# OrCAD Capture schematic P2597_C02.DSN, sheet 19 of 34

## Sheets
19 15_Serial port and JTAG: size Custom
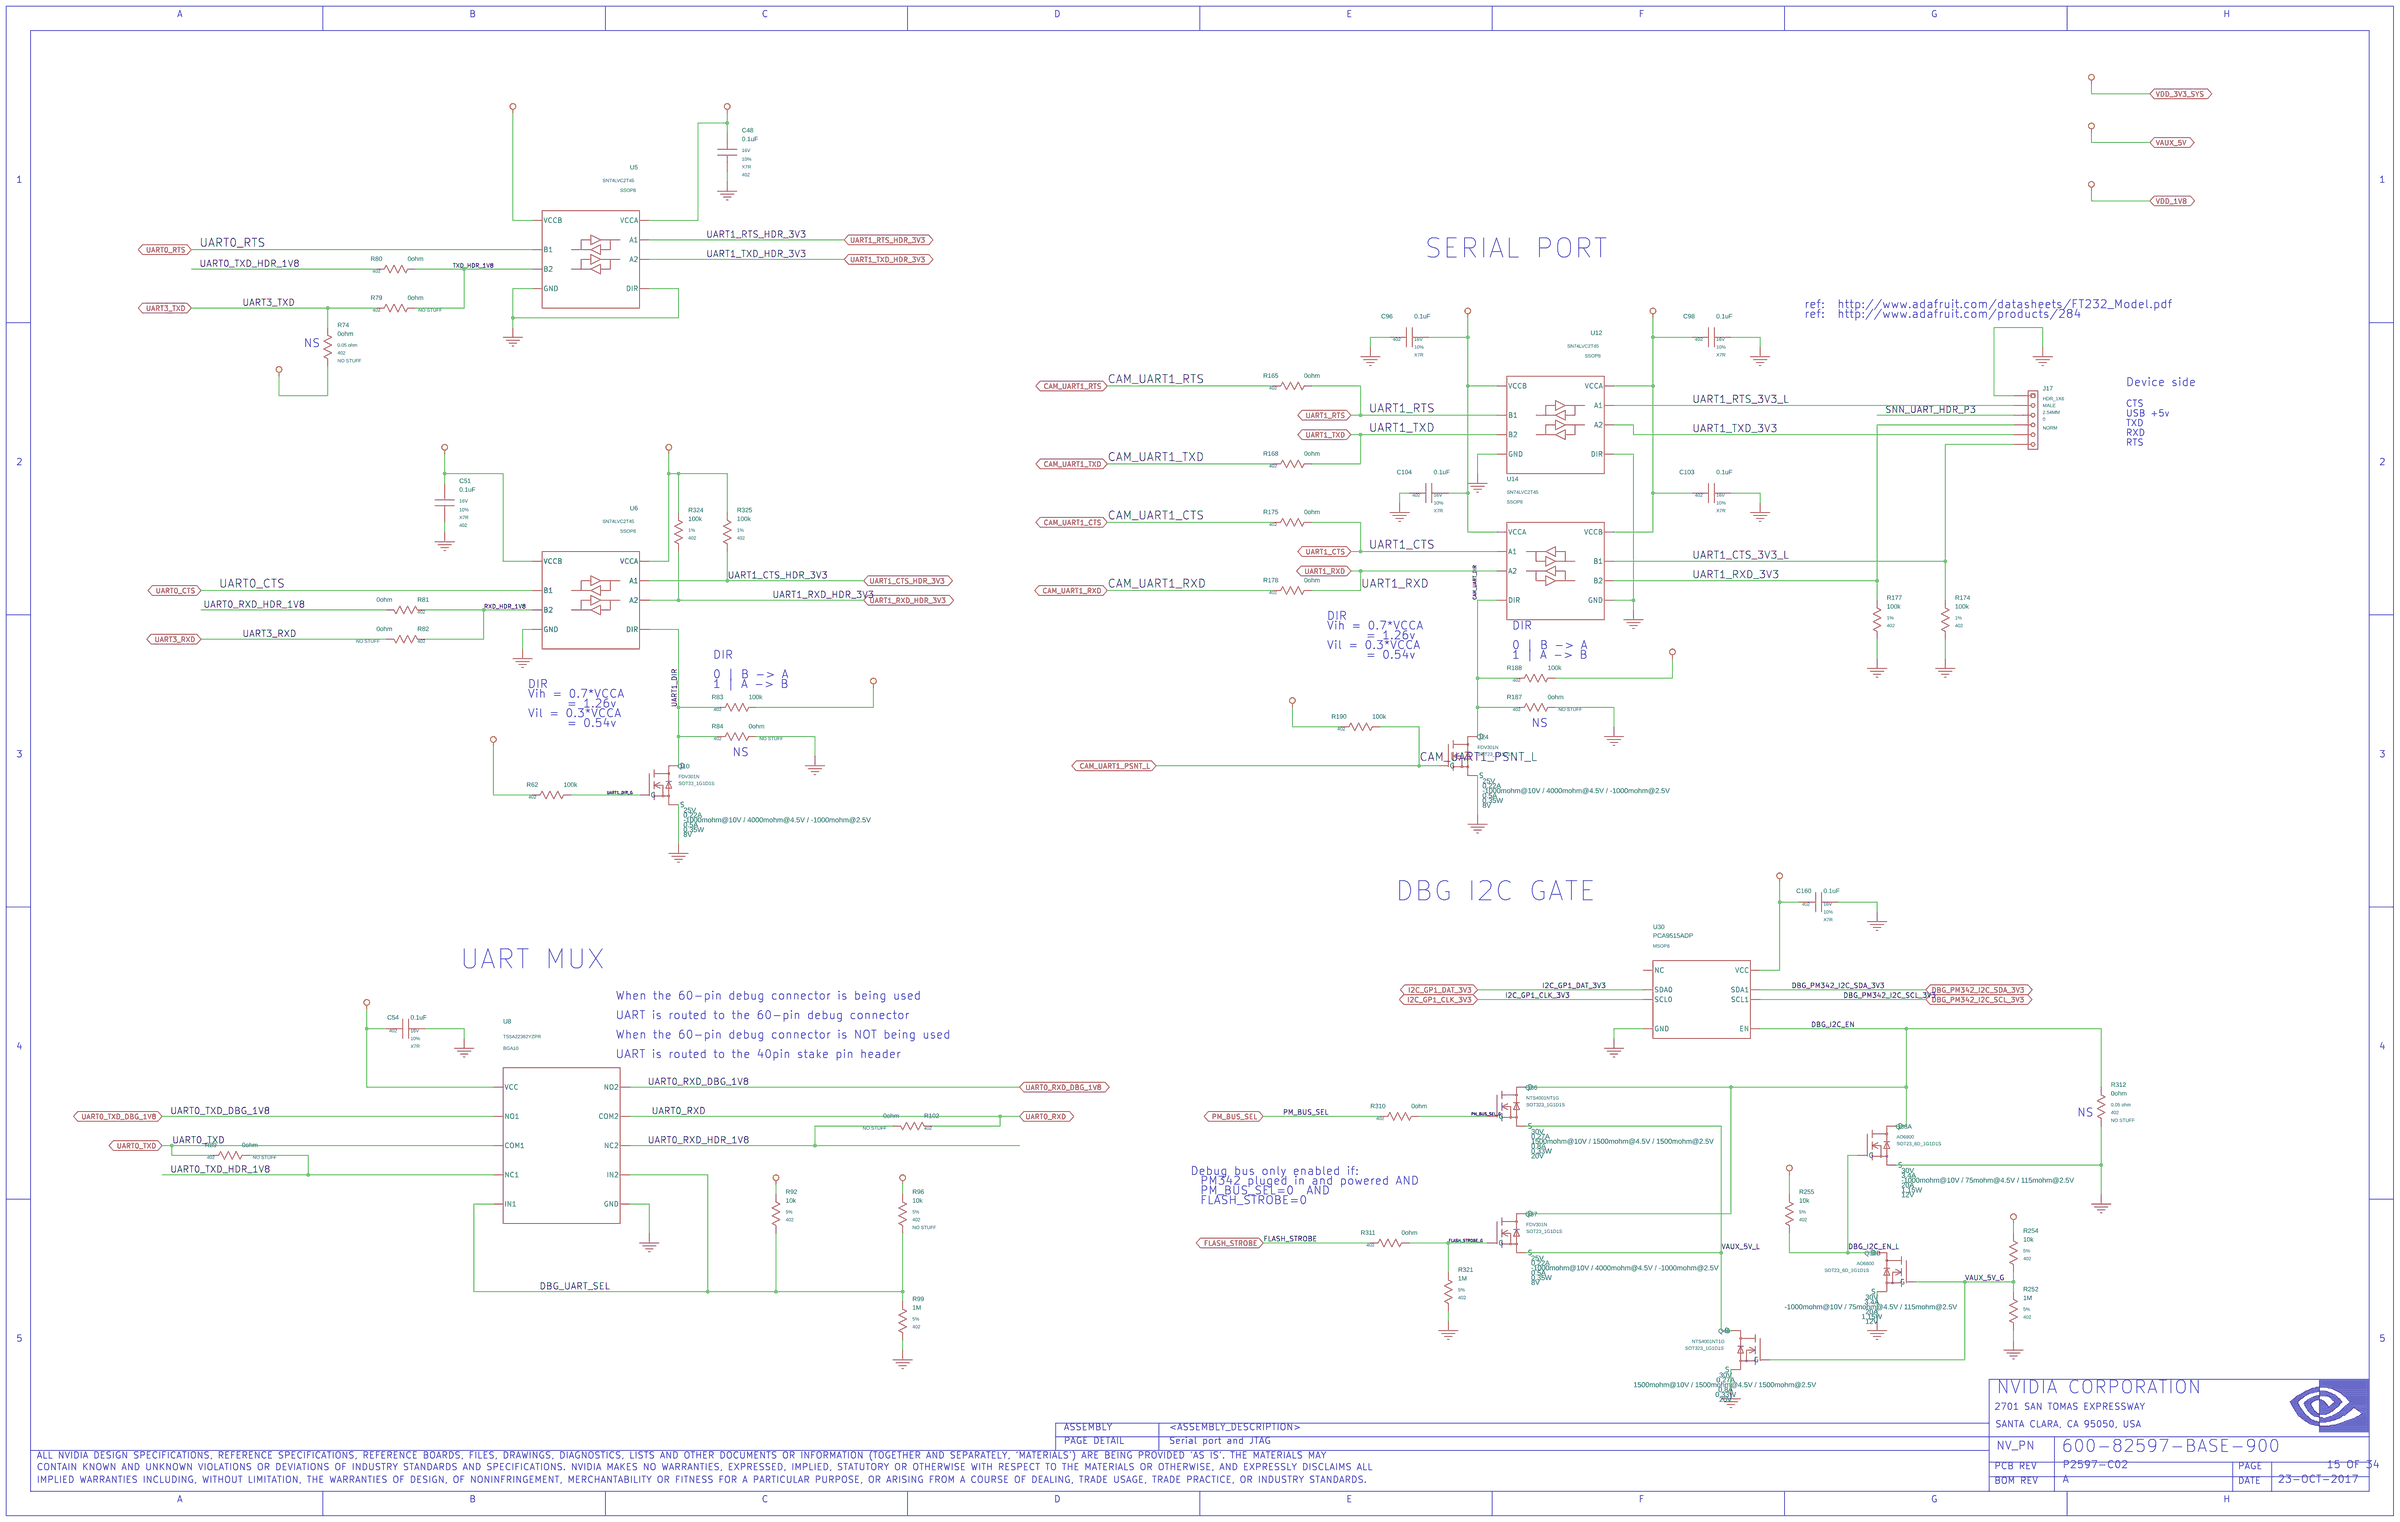
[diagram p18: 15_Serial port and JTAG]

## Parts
C48  0.1uF  [402]
C51  0.1uF  [402]
C54  0.1uF  [402]
C96  0.1uF  [402]
C98  0.1uF  [402]
C103  0.1uF  [402]
C104  0.1uF  [402]
C160  0.1uF  [402]
J17  HDR_1X6  [CON_HDR_001X006_TH_ST_M_P025]
Q10  Q_FET_N_ENH  [SOT23]
Q24  Q_FET_N_ENH  [SOT23]
Q36  Q_FET_N_ENH  [SOT323]
Q37  Q_FET_N_ENH  [SOT23]
Q38  Q_FET_N_ENH  [SOT23_6]  (sections A,B)
Q40  Q_FET_N_ENH  [SOT323]
R62  100k  [402]
R74  0ohm  [402]
R79  0ohm  [402]
R80  0ohm  [402]
R81  0ohm  [402]
R82  0ohm  [402]
R83  100k  [402]
R84  0ohm  [402]
R89  0ohm  [402]
R92  10k  [402]
R96  10k  [402]
R99  1M  [402]
R102  0ohm  [402]
R165  0ohm  [402]
R168  0ohm  [402]
R174  100k  [402]
R175  0ohm  [402]
R177  100k  [402]
R178  0ohm  [402]
R187  0ohm  [402]
R188  100k  [402]
R190  100k  [402]
R252  1M  [402]
R254  10k  [402]
R255  10k  [402]
R310  0ohm  [402]
R311  0ohm  [402]
R312  0ohm  [402]
R321  1M  [402]
R324  100k  [402]
R325  100k  [402]
U5  U_LEVSHFT_3STATE  [XSOP08_P065_030X028]
U6  U_LEVSHFT_3STATE  [XSOP08_P065_030X028]
U8  U_SW_ANA_SPDT  [BGA_0010_P050_013X020_MARK_A3]
U12  U_LEVSHFT_3STATE  [XSOP08_P065_030X028]
U14  U_LEVSHFT_3STATE  [XSOP08_P065_030X028]
U30  U_I2C_PCA9515A  [XSOP08_P065_030X030]

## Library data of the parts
C48 = C: ASSEMBLY: DEBUG; CDS_LIB: discrete; CDS_PART_NAME: C_0402-0.1UF,X7R,10%,16V,036-0014-000; CDS_PHYS_PART_NAME: C_0402-0.1UF,X7R,10%,16V,036-0014-000-0.1UF,036-0014-000; CDS_SEC: 1; DEVICE_TYPENAME: C_0402-01UFX7R1016V036-0014-000-01UF036-0014-000; DRAWING: @P2597_C02_LIB.P2597_C02(SCH_1):PAGE15; MAT: X7R; MAX_VOLTAGE: 16V; NV_PN: 036-0014-000; PATH: I346; PHYS_PAGE: 15; ROT: 0; SEC: 1; SIGNAL_MODEL: nv_cap; TOL: 10%; VER: 1; XY: (-7200,7550)
C51 = C: ASSEMBLY: DEBUG; CDS_LIB: discrete; CDS_PART_NAME: C_0402-0.1UF,X7R,10%,16V,036-0014-000; CDS_PHYS_PART_NAME: C_0402-0.1UF,X7R,10%,16V,036-0014-000-0.1UF,036-0014-000; CDS_SEC: 1; DEVICE_TYPENAME: C_0402-01UFX7R1016V036-0014-000-01UF036-0014-000; DRAWING: @P2597_C02_LIB.P2597_C02(SCH_1):PAGE15; MAT: X7R; MAX_VOLTAGE: 16V; NV_PN: 036-0014-000; PATH: I359; PHYS_PAGE: 15; ROT: 0; SEC: 1; SIGNAL_MODEL: nv_cap; TOL: 10%; VER: 1; XY: (-8650,5750)
C54 = C#1: ASSEMBLY: DEBUG; CDS_LIB: discrete; CDS_PART_NAME: C_0402-0.1UF,X7R,10%,16V,036-0014-000; CDS_PHYS_PART_NAME: C_0402-0.1UF,X7R,10%,16V,036-0014-000-0.1UF,036-0014-000; CDS_SEC: 1; CHIPS_PART_NAME: C; DEVICE_TYPENAME: C_0402-01UFX7R1016V036-0014-000-01UF036-0014-000; DRAWING: @P2597_C02_LIB.P2597_C02(SCH_1):PAGE15; ESL: N/A; ESR: N/A; MAT: X7R; MAX_VOLTAGE: 16V; NV_PN: 036-0014-000; PATH: I372; PHYS_PAGE: 15; ROT: 0; SEC: 1; SIGNAL_MODEL: nv_cap; TOL: 10%; VER: 2; XY: (-8850,3050)
C96 = C#1: ASSEMBLY: DEBUG; CDS_LIB: discrete; CDS_PART_NAME: C_0402-0.1UF,X7R,10%,16V,036-0014-000; CDS_PHYS_PART_NAME: C_0402-0.1UF,X7R,10%,16V,036-0014-000-0.1UF,036-0014-000; CDS_SEC: 1; CHIPS_PART_NAME: C; DEVICE_TYPENAME: C_0402-01UFX7R1016V036-0014-000-01UF036-0014-000; DRAWING: @P2597_C02_LIB.P2597_C02(SCH_1):PAGE15; MAT: X7R; MAX_VOLTAGE: 16V; NV_PN: 036-0014-000; PATH: I89; PHYS_PAGE: 15; ROT: 0; SEC: 1; SIGNAL_MODEL: nv_cap; TOL: 10%; VER: 2; XY: (-3700,6600)
C98 = C#1: ASSEMBLY: DEBUG; CDS_LIB: discrete; CDS_PART_NAME: C_0402-0.1UF,X7R,10%,16V,036-0014-000; CDS_PHYS_PART_NAME: C_0402-0.1UF,X7R,10%,16V,036-0014-000-0.1UF,036-0014-000; CDS_SEC: 1; CHIPS_PART_NAME: C; DEVICE_TYPENAME: C_0402-01UFX7R1016V036-0014-000-01UF036-0014-000; DRAWING: @P2597_C02_LIB.P2597_C02(SCH_1):PAGE15; MAT: X7R; MAX_VOLTAGE: 16V; NV_PN: 036-0014-000; PATH: I91; PHYS_PAGE: 15; ROT: 0; SEC: 1; SIGNAL_MODEL: nv_cap; TOL: 10%; VER: 2; XY: (-2150,6600)
C103 = C#1: ASSEMBLY: DEBUG; CDS_LIB: discrete; CDS_PART_NAME: C_0402-0.1UF,X7R,10%,16V,036-0014-000; CDS_PHYS_PART_NAME: C_0402-0.1UF,X7R,10%,16V,036-0014-000-0.1UF,036-0014-000; CDS_SEC: 1; CHIPS_PART_NAME: C; DEVICE_TYPENAME: C_0402-01UFX7R1016V036-0014-000-01UF036-0014-000; DRAWING: @P2597_C02_LIB.P2597_C02(SCH_1):PAGE15; MAT: X7R; MAX_VOLTAGE: 16V; NV_PN: 036-0014-000; PATH: I92; PHYS_PAGE: 15; ROT: 0; SEC: 1; SIGNAL_MODEL: nv_cap; TOL: 10%; VER: 2; XY: (-2150,5800)
C104 = C#1: ASSEMBLY: DEBUG; CDS_LIB: discrete; CDS_PART_NAME: C_0402-0.1UF,X7R,10%,16V,036-0014-000; CDS_PHYS_PART_NAME: C_0402-0.1UF,X7R,10%,16V,036-0014-000-0.1UF,036-0014-000; CDS_SEC: 1; CHIPS_PART_NAME: C; DEVICE_TYPENAME: C_0402-01UFX7R1016V036-0014-000-01UF036-0014-000; DRAWING: @P2597_C02_LIB.P2597_C02(SCH_1):PAGE15; MAT: X7R; MAX_VOLTAGE: 16V; NV_PN: 036-0014-000; PATH: I90; PHYS_PAGE: 15; ROT: 0; SEC: 1; SIGNAL_MODEL: nv_cap; TOL: 10%; VER: 2; XY: (-3600,5800)
C160 = C#1: ASSEMBLY: DEBUG; CDS_LIB: discrete; CDS_PART_NAME: C_0402-0.1UF,X7R,10%,16V,036-0014-000; CDS_PHYS_PART_NAME: C_0402-0.1UF,X7R,10%,16V,036-0014-000-0.1UF,036-0014-000; CDS_SEC: 1; CHIPS_PART_NAME: C; DEVICE_TYPENAME: C_0402-01UFX7R1016V036-0014-000-01UF036-0014-000; DRAWING: @P2597_C02_LIB.P2597_C02(SCH_1):PAGE15; ESL: N/A; ESR: N/A; MAT: X7R; MAX_VOLTAGE: 16V; NV_PN: 036-0014-000; PATH: I446; PHYS_PAGE: 15; ROT: 0; SEC: 1; SIGNAL_MODEL: nv_cap; TOL: 10%; VER: 2; XY: (-1600,3700)
J17 = HDR_1X6: ANGLE: 0; ASSEMBLY: DEBUG; CDS_LIB: electro_mechanic; CDS_PART_NAME: HDR_1X6_NORM-HDR_1X6,MALE,2.54MM,0,YES,NO,NO,450V,3.0A,074-0050-000; CDS_PHYS_PART_NAME: HDR_1X6_NORM-HDR_1X6,MALE,2.54MM,0,YES,NO,NO,450V,3.0A,074-0050-000-074-0050-000; CDS_SEC: 1; DEVICE_TYPENAME: HDR_1X6_NORM-HDR_1X6MALE254MM0YESNONO450V30A074-0050-000-074-0050-000; DRAWING: @P2597_C02_LIB.P2597_C02(SCH_1):PAGE15; GENDER: MALE; LATCHING: NO; MAX_CURRENT: 3.0A; MAX_VOLTAGE: 450V; NV_PN: 074-0050-000; PACK_TYPE: NORM; PATH: I302; PHYS_PAGE: 15; PITCH: 2.54MM; REFLOW: YES; ROT: 0; SEC: 1; SEC_TYPE: NORM; SHROUDED: NO; VER: 1; XY: (-500,6300)
Q10 = Q_FET_N_ENH#2: ASSEMBLY: DEBUG; CDS_LIB: discrete; CDS_PART_NAME: Q_FET_N_ENH_SOT23_1G1D1S-FDV301N,25V,-1000MOHM@10V / 4000MOHM@4.5V / -1000MOHM@2.5V,0.22A,0.5A,8V,0.35W,[ ]@10V / [ ]@4.5V / [A; CDS_PHYS_PART_NAME: Q_FET_N_ENH_SOT23_1G1D1S-FDV301N,25V,-1000MOHM@10V / 4000MOHM@4.5V / -1000MOHM@2.5V,0.22A,0.5A,8V,0.35W,[ ]@10V / [ ]@4.5V / [B; CDS_SEC: 1; CONTINUOUS_CURRENT: 0.22A; CaptureCellPackProp: Q_FET_N_ENH__sym_2##2; DEVICE_TYPENAME: Q_FET_N_ENH_SOT23_1G1D1S-FDV301N25V-1000MOHM10V4000MOHM45V-1000MOHM25V022A05A8V035W10V45VB; DRAWING: @P2597_C02_LIB.P2597_C02(SCH_1):PAGE15; MAX_CURRENT: 0.5A; MAX_VOLTAGE: 25V; MAX_WATTAGE: 0.35W; NV_NAME: FDV301N; NV_PN: 300-0494-000; PACK_TYPE: SOT23_1G1D1S; PATH: I426; PHYS_PAGE: 15; Q_G: [ ]@10V / [ ]@4.5V / [ ]@2.5V; ROT: 0; R_DS_ON: -1000mohm@10V / 4000mohm@4.5V / -1000mohm@2.5V; SEC: 1; VER: 2; V_BE_GS: 8V; XY: (-7550,4300)
Q24 = Q_FET_N_ENH#2: ASSEMBLY: DEBUG; CDS_LIB: discrete; CDS_PART_NAME: Q_FET_N_ENH_SOT23_1G1D1S-FDV301N,25V,-1000MOHM@10V / 4000MOHM@4.5V / -1000MOHM@2.5V,0.22A,0.5A,8V,0.35W,[ ]@10V / [ ]@4.5V / [A; CDS_PHYS_PART_NAME: Q_FET_N_ENH_SOT23_1G1D1S-FDV301N,25V,-1000MOHM@10V / 4000MOHM@4.5V / -1000MOHM@2.5V,0.22A,0.5A,8V,0.35W,[ ]@10V / [ ]@4.5V / [B; CDS_SEC: 1; CONTINUOUS_CURRENT: 0.22A; CaptureCellPackProp: Q_FET_N_ENH__sym_2##2; DEVICE_TYPENAME: Q_FET_N_ENH_SOT23_1G1D1S-FDV301N25V-1000MOHM10V4000MOHM45V-1000MOHM25V022A05A8V035W10V45VB; DRAWING: @P2597_C02_LIB.P2597_C02(SCH_1):PAGE15; MAX_CURRENT: 0.5A; MAX_VOLTAGE: 25V; MAX_WATTAGE: 0.35W; NV_NAME: FDV301N; NV_PN: 300-0494-000; PACK_TYPE: SOT23_1G1D1S; PATH: I410; PHYS_PAGE: 15; Q_G: [ ]@10V / [ ]@4.5V / [ ]@2.5V; ROT: 0; R_DS_ON: -1000mohm@10V / 4000mohm@4.5V / -1000mohm@2.5V; SEC: 1; VER: 2; V_BE_GS: 8V; XY: (-3450,4450)
Q36 = Q_FET_N_ENH#2: ASSEMBLY: DEBUG; CDS_LIB: discrete; CDS_PART_NAME: Q_FET_N_ENH_SOT323_1G1D1S-NTS4001NT1G,30V,1500MOHM@10V / 1500MOHM@4.5V / 1500MOHM@2.5V,0.27A,0.8A,20V,0.33W,[ ]@10V / [ ]@4.5VA; CDS_PHYS_PART_NAME: Q_FET_N_ENH_SOT323_1G1D1S-NTS4001NT1G,30V,1500MOHM@10V / 1500MOHM@4.5V / 1500MOHM@2.5V,0.27A,0.8A,20V,0.33W,[ ]@10V / [ ]@4.5VB; CDS_SEC: 1; CONTINUOUS_CURRENT: 0.27A; CaptureCellPackProp: Q_FET_N_ENH__sym_2##2; DEVICE_TYPENAME: Q_FET_N_ENH_SOT323_1G1D1S-NTS4001NT1G30V1500MOHM10V1500MOHM45V1500MOHM25V027A08A20V033W10V45VB; DRAWING: @P2597_C02_LIB.P2597_C02(SCH_1):PAGE15; MAX_CURRENT: 0.8A; MAX_VOLTAGE: 30V; MAX_WATTAGE: 0.33W; NV_NAME: NTS4001NT1G; NV_PN: 300-0485-000; PACK_TYPE: SOT323_1G1D1S; PATH: I481; PHYS_PAGE: 15; Q_G: [ ]@10V / [ ]@4.5V / [ ]@2.5V; ROT: 0; R_DS_ON: 1500mohm@10V / 1500mohm@4.5V / 1500mohm@2.5V; SEC: 1; SEC_TYPE: SOT323_1G1D1S; VER: 2; V_BE_GS: 20V; XY: (-3200,2650)
Q37 = Q_FET_N_ENH#2: ASSEMBLY: DEBUG; CDS_LIB: discrete; CDS_PART_NAME: Q_FET_N_ENH_SOT23_1G1D1S-FDV301N,25V,-1000MOHM@10V / 4000MOHM@4.5V / -1000MOHM@2.5V,0.22A,0.5A,8V,0.35W,[ ]@10V / [ ]@4.5V / [A; CDS_PHYS_PART_NAME: Q_FET_N_ENH_SOT23_1G1D1S-FDV301N,25V,-1000MOHM@10V / 4000MOHM@4.5V / -1000MOHM@2.5V,0.22A,0.5A,8V,0.35W,[ ]@10V / [ ]@4.5V / [B; CDS_SEC: 1; CONTINUOUS_CURRENT: 0.22A; CaptureCellPackProp: Q_FET_N_ENH__sym_2##2; DEVICE_TYPENAME: Q_FET_N_ENH_SOT23_1G1D1S-FDV301N25V-1000MOHM10V4000MOHM45V-1000MOHM25V022A05A8V035W10V45VB; DRAWING: @P2597_C02_LIB.P2597_C02(SCH_1):PAGE15; MAX_CURRENT: 0.5A; MAX_VOLTAGE: 25V; MAX_WATTAGE: 0.35W; NV_NAME: FDV301N; NV_PN: 300-0494-000; PACK_TYPE: SOT23_1G1D1S; PATH: I480; PHYS_PAGE: 15; Q_G: [ ]@10V / [ ]@4.5V / [ ]@2.5V; ROT: 0; R_DS_ON: -1000mohm@10V / 4000mohm@4.5V / -1000mohm@2.5V; SEC: 1; SEC_TYPE: SOT23_1G1D1S; VER: 2; V_BE_GS: 8V; XY: (-3200,2000)
Q38 = Q_FET_N_ENH: ASSEMBLY: DEBUG; CDS_LIB: discrete; CDS_PART_NAME: Q_FET_N_ENH_SOT23_6D_1G1D1S-AO6800,30V,-1000MOHM@10V / 75MOHM@4.5V / 115MOHM@2.5V,3.4A,20A,12V,1.15W,[ ]@10V / [ ]@4.5V / [ ]@A; CDS_PHYS_PART_NAME: Q_FET_N_ENH_SOT23_6D_1G1D1S-AO6800,30V,-1000MOHM@10V / 75MOHM@4.5V / 115MOHM@2.5V,3.4A,20A,12V,1.15W,[ ]@10V / [ ]@4.5V / [ ]@B; CDS_SEC: 2; CONTINUOUS_CURRENT: 3.4A; DEVICE_TYPENAME: Q_FET_N_ENH_SOT23_6D_1G1D1S-AO680030V-1000MOHM10V75MOHM45V115MOHM25V34A20A12V115W10V45VB; DRAWING: @P2597_C02_LIB.P2597_C02(SCH_1):PAGE15; MAX_CURRENT: 20A; MAX_VOLTAGE: 30V; MAX_WATTAGE: 1.15W; NV_NAME: AO6800; NV_PN: 300-0634-000; PACK_TYPE: SOT23_6D_1G1D1S; PATH: I472; PHYS_PAGE: 15; Q_G: [ ]@10V / [ ]@4.5V / [ ]@2.5V; ROT: 2; R_DS_ON: -1000mohm@10V / 75mohm@4.5V / 115mohm@2.5V; SEC: 2; SEC_TYPE: SOT23_6D_1G1D1S; VER: 2; V_BE_GS: 12V; XY: (-1200,1800)
Q40 = Q_FET_N_ENH#2: ASSEMBLY: DEBUG; CDS_LIB: discrete; CDS_PART_NAME: Q_FET_N_ENH_SOT323_1G1D1S-NTS4001NT1G,30V,1500MOHM@10V / 1500MOHM@4.5V / 1500MOHM@2.5V,0.27A,0.8A,20V,0.33W,[ ]@10V / [ ]@4.5VA; CDS_PHYS_PART_NAME: Q_FET_N_ENH_SOT323_1G1D1S-NTS4001NT1G,30V,1500MOHM@10V / 1500MOHM@4.5V / 1500MOHM@2.5V,0.27A,0.8A,20V,0.33W,[ ]@10V / [ ]@4.5VB; CDS_SEC: 1; CONTINUOUS_CURRENT: 0.27A; CaptureCellPackProp: Q_FET_N_ENH__sym_2##2; DEVICE_TYPENAME: Q_FET_N_ENH_SOT323_1G1D1S-NTS4001NT1G30V1500MOHM10V1500MOHM45V1500MOHM25V027A08A20V033W10V45VB; DRAWING: @P2597_C02_LIB.P2597_C02(SCH_1):PAGE15; MAX_CURRENT: 0.8A; MAX_VOLTAGE: 30V; MAX_WATTAGE: 0.33W; NV_NAME: NTS4001NT1G; NV_PN: 300-0485-000; PACK_TYPE: SOT323_1G1D1S; PATH: I482; PHYS_PAGE: 15; Q_G: [ ]@10V / [ ]@4.5V / [ ]@2.5V; ROT: 2; R_DS_ON: 1500mohm@10V / 1500mohm@4.5V / 1500mohm@2.5V; SEC: 1; SEC_TYPE: SOT323_1G1D1S; VER: 2; V_BE_GS: 20V; XY: (-1950,1400)
R62 = R: ASSEMBLY: DEBUG; CDS_LIB: discrete; CDS_PART_NAME: R_0402-100K,1 %,62.5MW,195-0005-000; CDS_PHYS_PART_NAME: R_0402-100K,1 %,62.5MW,195-0005-000-100K,195-0005-000; CDS_SEC: 1; DEVICE_TYPENAME: R_0402-100K1625MW195-0005-000-100K195-0005-000; DRAWING: @P2597_C02_LIB.P2597_C02(SCH_1):PAGE15; MAX_WATTAGE: 62.5mW; NV_PN: 195-0005-000; PATH: I427; PHYS_PAGE: 15; ROT: 0; SEC: 1; SIGNAL_MODEL: nv_res; TOL: 1%; VER: 1; XY: (-8100,4250)
R74 = R#1: ASSEMBLY: DEBUG; CDS_LIB: discrete; CDS_PART_NAME: R_0402-0OHM,0.05 OHM,62.5MW,195-2655-000; CDS_PHYS_PART_NAME: R_0402-0OHM,0.05 OHM,62.5MW,195-2655-000-0OHM,195-2655-000; CDS_SEC: 1; CHIPS_PART_NAME: R; DEVICE_TYPENAME: R_0402-0OHM005OHM625MW195-2655-000-0OHM195-2655-000; DRAWING: @P2597_C02_LIB.P2597_C02(SCH_1):PAGE15; MAX_WATTAGE: 62.5mW; NV_PN: 195-2655-000; PATH: I431; PHYS_PAGE: 15; ROT: 0; SEC: 1; SIGNAL_MODEL: nv_res; SKU: NO STUFF; TOL: 0.05 ohm; VER: 2; XY: (-9250,6550)
R79 = R: ASSEMBLY: DEBUG; CDS_LIB: discrete; CDS_PART_NAME: R_0402-0OHM,0.05 OHM,62.5MW,195-2655-000; CDS_PHYS_PART_NAME: R_0402-0OHM,0.05 OHM,62.5MW,195-2655-000-0OHM,195-2655-000; CDS_SEC: 1; DEVICE_TYPENAME: R_0402-0OHM005OHM625MW195-2655-000-0OHM195-2655-000; DRAWING: @P2597_C02_LIB.P2597_C02(SCH_1):PAGE15; MAX_WATTAGE: 62.5mW; NV_PN: 195-2655-000; PATH: I392; PHYS_PAGE: 15; ROT: 0; SEC: 1; SIGNAL_MODEL: nv_res; SKU: NO STUFF; TOL: 0.05 ohm; VER: 1; XY: (-8900,6750)
R80 = R: ASSEMBLY: DEBUG; CDS_LIB: discrete; CDS_PART_NAME: R_0402-0OHM,0.05 OHM,62.5MW,195-2655-000; CDS_PHYS_PART_NAME: R_0402-0OHM,0.05 OHM,62.5MW,195-2655-000-0OHM,195-2655-000; CDS_SEC: 1; DEVICE_TYPENAME: R_0402-0OHM005OHM625MW195-2655-000-0OHM195-2655-000; DRAWING: @P2597_C02_LIB.P2597_C02(SCH_1):PAGE15; MAX_WATTAGE: 62.5mW; NV_PN: 195-2655-000; PATH: I391; PHYS_PAGE: 15; ROT: 0; SEC: 1; SIGNAL_MODEL: nv_res; TOL: 0.05 ohm; VER: 1; XY: (-8900,6950)
R81 = R: ASSEMBLY: DEBUG; CDS_LIB: discrete; CDS_PART_NAME: R_0402-0OHM,0.05 OHM,62.5MW,195-2655-000; CDS_PHYS_PART_NAME: R_0402-0OHM,0.05 OHM,62.5MW,195-2655-000-0OHM,195-2655-000; CDS_SEC: 1; DEVICE_TYPENAME: R_0402-0OHM005OHM625MW195-2655-000-0OHM195-2655-000; DRAWING: @P2597_C02_LIB.P2597_C02(SCH_1):PAGE15; MAX_WATTAGE: 62.5mW; NV_PN: 195-2655-000; PATH: I393; PHYS_PAGE: 15; ROT: 2; SEC: 1; SIGNAL_MODEL: nv_res; TOL: 0.05 ohm; VER: 1; XY: (-8850,5200)
R82 = R: ASSEMBLY: DEBUG; CDS_LIB: discrete; CDS_PART_NAME: R_0402-0OHM,0.05 OHM,62.5MW,195-2655-000; CDS_PHYS_PART_NAME: R_0402-0OHM,0.05 OHM,62.5MW,195-2655-000-0OHM,195-2655-000; CDS_SEC: 1; DEVICE_TYPENAME: R_0402-0OHM005OHM625MW195-2655-000-0OHM195-2655-000; DRAWING: @P2597_C02_LIB.P2597_C02(SCH_1):PAGE15; MAX_WATTAGE: 62.5mW; NV_PN: 195-2655-000; PATH: I394; PHYS_PAGE: 15; ROT: 2; SEC: 1; SIGNAL_MODEL: nv_res; SKU: NO STUFF; TOL: 0.05 ohm; VER: 1; XY: (-8850,5050)
R83 = R: ASSEMBLY: DEBUG; CDS_LIB: discrete; CDS_PART_NAME: R_0402-100K,1 %,62.5MW,195-0005-000; CDS_PHYS_PART_NAME: R_0402-100K,1 %,62.5MW,195-0005-000-100K,195-0005-000; CDS_SEC: 1; DEVICE_TYPENAME: R_0402-100K1625MW195-0005-000-100K195-0005-000; DRAWING: @P2597_C02_LIB.P2597_C02(SCH_1):PAGE15; MAX_WATTAGE: 62.5mW; NV_PN: 195-0005-000; PATH: I424; PHYS_PAGE: 15; ROT: 0; SEC: 1; SIGNAL_MODEL: nv_res; TOL: 1%; VER: 1; XY: (-7150,4700)
R84 = R: ASSEMBLY: DEBUG; CDS_LIB: discrete; CDS_PART_NAME: R_0402-0OHM,0.05 OHM,62.5MW,195-2655-000; CDS_PHYS_PART_NAME: R_0402-0OHM,0.05 OHM,62.5MW,195-2655-000-0OHM,195-2655-000; CDS_SEC: 1; DEVICE_TYPENAME: R_0402-0OHM005OHM625MW195-2655-000-0OHM195-2655-000; DRAWING: @P2597_C02_LIB.P2597_C02(SCH_1):PAGE15; MAX_WATTAGE: 62.5mW; NV_PN: 195-2655-000; PATH: I425; PHYS_PAGE: 15; ROT: 0; SEC: 1; SIGNAL_MODEL: nv_res; SKU: NO STUFF; TOL: 0.05 ohm; VER: 1; XY: (-7150,4550)
R89 = R: ASSEMBLY: DEBUG; CDS_LIB: discrete; CDS_PART_NAME: R_0402-0OHM,0.05 OHM,62.5MW,195-2655-000; CDS_PHYS_PART_NAME: R_0402-0OHM,0.05 OHM,62.5MW,195-2655-000-0OHM,195-2655-000; CDS_SEC: 1; DEVICE_TYPENAME: R_0402-0OHM005OHM625MW195-2655-000-0OHM195-2655-000; DRAWING: @P2597_C02_LIB.P2597_C02(SCH_1):PAGE15; MAX_WATTAGE: 62.5mW; NV_PN: 195-2655-000; PATH: I387; PHYS_PAGE: 15; ROT: 0; SEC: 1; SIGNAL_MODEL: nv_res; SKU: NO STUFF; TOL: 0.05 ohm; VER: 1; XY: (-9750,2400)
R92 = R#1: ASSEMBLY: DEBUG; CDS_LIB: discrete; CDS_PART_NAME: R_0402-10K,5 %,62.5MW,195-0486-000; CDS_PHYS_PART_NAME: R_0402-10K,5 %,62.5MW,195-0486-000-10K,195-0486-000; CDS_SEC: 1; CHIPS_PART_NAME: R; DEVICE_TYPENAME: R_0402-10K5625MW195-0486-000-10K195-0486-000; DRAWING: @P2597_C02_LIB.P2597_C02(SCH_1):PAGE15; MAX_WATTAGE: 62.5mW; NV_PN: 195-0486-000; PATH: I328; PHYS_PAGE: 15; ROT: 0; SEC: 1; SIGNAL_MODEL: nv_res; TOL: 5%; VER: 2; XY: (-6950,2100)
R96 = R#1: ASSEMBLY: DEBUG; CDS_LIB: discrete; CDS_PART_NAME: R_0402-10K,5 %,62.5MW,195-0486-000; CDS_PHYS_PART_NAME: R_0402-10K,5 %,62.5MW,195-0486-000-10K,195-0486-000; CDS_SEC: 1; CHIPS_PART_NAME: R; DEVICE_TYPENAME: R_0402-10K5625MW195-0486-000-10K195-0486-000; DRAWING: @P2597_C02_LIB.P2597_C02(SCH_1):PAGE15; MAX_WATTAGE: 62.5mW; NV_PN: 195-0486-000; PATH: I390; PHYS_PAGE: 15; ROT: 0; SEC: 1; SIGNAL_MODEL: nv_res; SKU: NO STUFF; TOL: 5%; VER: 2; XY: (-6300,2100)
R99 = R#1: ASSEMBLY: DEBUG; CDS_LIB: discrete; CDS_PART_NAME: R_0402-1M,5 %,62.5MW,195-0488-000; CDS_PHYS_PART_NAME: R_0402-1M,5 %,62.5MW,195-0488-000-195-0488-000,1M; CDS_SEC: 1; CHIPS_PART_NAME: R; DEVICE_TYPENAME: R_0402-1M5625MW195-0488-000-195-0488-0001M; DRAWING: @P2597_C02_LIB.P2597_C02(SCH_1):PAGE15; MAX_WATTAGE: 62.5mW; NV_PN: 195-0488-000; PATH: I362; PHYS_PAGE: 15; ROT: 0; SEC: 1; SIGNAL_MODEL: nv_res; TOL: 5%; VER: 2; XY: (-6300,1550)
R102 = R: ASSEMBLY: DEBUG; CDS_LIB: discrete; CDS_PART_NAME: R_0402-0OHM,0.05 OHM,62.5MW,195-2655-000; CDS_PHYS_PART_NAME: R_0402-0OHM,0.05 OHM,62.5MW,195-2655-000-0OHM,195-2655-000; CDS_SEC: 1; DEVICE_TYPENAME: R_0402-0OHM005OHM625MW195-2655-000-0OHM195-2655-000; DRAWING: @P2597_C02_LIB.P2597_C02(SCH_1):PAGE15; MAX_WATTAGE: 62.5mW; NV_PN: 195-2655-000; PATH: I385; PHYS_PAGE: 15; ROT: 2; SEC: 1; SIGNAL_MODEL: nv_res; SKU: NO STUFF; TOL: 0.05 ohm; VER: 1; XY: (-6250,2550)
R165 = R: ASSEMBLY: DEBUG; CDS_LIB: discrete; CDS_PART_NAME: R_0402-0OHM,0.05 OHM,62.5MW,195-2655-000; CDS_PHYS_PART_NAME: R_0402-0OHM,0.05 OHM,62.5MW,195-2655-000-0OHM,195-2655-000; CDS_SEC: 1; DEVICE_TYPENAME: R_0402-0OHM005OHM625MW195-2655-000-0OHM195-2655-000; DRAWING: @P2597_C02_LIB.P2597_C02(SCH_1):PAGE15; MAX_WATTAGE: 62.5mW; NV_PN: 195-2655-000; PATH: I397; PHYS_PAGE: 15; ROT: 0; SEC: 1; SIGNAL_MODEL: nv_res; TOL: 0.05 ohm; VER: 1; XY: (-4300,6350)
R168 = R: ASSEMBLY: DEBUG; CDS_LIB: discrete; CDS_PART_NAME: R_0402-0OHM,0.05 OHM,62.5MW,195-2655-000; CDS_PHYS_PART_NAME: R_0402-0OHM,0.05 OHM,62.5MW,195-2655-000-0OHM,195-2655-000; CDS_SEC: 1; DEVICE_TYPENAME: R_0402-0OHM005OHM625MW195-2655-000-0OHM195-2655-000; DRAWING: @P2597_C02_LIB.P2597_C02(SCH_1):PAGE15; MAX_WATTAGE: 62.5mW; NV_PN: 195-2655-000; PATH: I398; PHYS_PAGE: 15; ROT: 0; SEC: 1; SIGNAL_MODEL: nv_res; TOL: 0.05 ohm; VER: 1; XY: (-4300,5950)
R174 = R#1: ASSEMBLY: DEBUG; CDS_LIB: discrete; CDS_PART_NAME: R_0402-100K,1 %,62.5MW,195-0005-000; CDS_PHYS_PART_NAME: R_0402-100K,1 %,62.5MW,195-0005-000-100K,195-0005-000; CDS_SEC: 1; CHIPS_PART_NAME: R; DEVICE_TYPENAME: R_0402-100K1625MW195-0005-000-100K195-0005-000; DRAWING: @P2597_C02_LIB.P2597_C02(SCH_1):PAGE15; MAX_WATTAGE: 62.5mW; NV_PN: 195-0005-000; PATH: I215; PHYS_PAGE: 15; ROT: 0; SEC: 1; SIGNAL_MODEL: nv_res; TOL: 1%; VER: 2; XY: (-950,5150)
R175 = R: ASSEMBLY: DEBUG; CDS_LIB: discrete; CDS_PART_NAME: R_0402-0OHM,0.05 OHM,62.5MW,195-2655-000; CDS_PHYS_PART_NAME: R_0402-0OHM,0.05 OHM,62.5MW,195-2655-000-0OHM,195-2655-000; CDS_SEC: 1; DEVICE_TYPENAME: R_0402-0OHM005OHM625MW195-2655-000-0OHM195-2655-000; DRAWING: @P2597_C02_LIB.P2597_C02(SCH_1):PAGE15; MAX_WATTAGE: 62.5mW; NV_PN: 195-2655-000; PATH: I399; PHYS_PAGE: 15; ROT: 0; SEC: 1; SIGNAL_MODEL: nv_res; TOL: 0.05 ohm; VER: 1; XY: (-4300,5650)
R177 = R#1: ASSEMBLY: DEBUG; CDS_LIB: discrete; CDS_PART_NAME: R_0402-100K,1 %,62.5MW,195-0005-000; CDS_PHYS_PART_NAME: R_0402-100K,1 %,62.5MW,195-0005-000-100K,195-0005-000; CDS_SEC: 1; CHIPS_PART_NAME: R; DEVICE_TYPENAME: R_0402-100K1625MW195-0005-000-100K195-0005-000; DRAWING: @P2597_C02_LIB.P2597_C02(SCH_1):PAGE15; MAX_WATTAGE: 62.5mW; NV_PN: 195-0005-000; PATH: I217; PHYS_PAGE: 15; ROT: 0; SEC: 1; SIGNAL_MODEL: nv_res; TOL: 1%; VER: 2; XY: (-1300,5150)
R178 = R: ASSEMBLY: DEBUG; CDS_LIB: discrete; CDS_PART_NAME: R_0402-0OHM,0.05 OHM,62.5MW,195-2655-000; CDS_PHYS_PART_NAME: R_0402-0OHM,0.05 OHM,62.5MW,195-2655-000-0OHM,195-2655-000; CDS_SEC: 1; DEVICE_TYPENAME: R_0402-0OHM005OHM625MW195-2655-000-0OHM195-2655-000; DRAWING: @P2597_C02_LIB.P2597_C02(SCH_1):PAGE15; MAX_WATTAGE: 62.5mW; NV_PN: 195-2655-000; PATH: I400; PHYS_PAGE: 15; ROT: 0; SEC: 1; SIGNAL_MODEL: nv_res; TOL: 0.05 ohm; VER: 1; XY: (-4300,5300)
R187 = R: ASSEMBLY: DEBUG; CDS_LIB: discrete; CDS_PART_NAME: R_0402-0OHM,0.05 OHM,62.5MW,195-2655-000; CDS_PHYS_PART_NAME: R_0402-0OHM,0.05 OHM,62.5MW,195-2655-000-0OHM,195-2655-000; CDS_SEC: 1; DEVICE_TYPENAME: R_0402-0OHM005OHM625MW195-2655-000-0OHM195-2655-000; DRAWING: @P2597_C02_LIB.P2597_C02(SCH_1):PAGE15; MAX_WATTAGE: 62.5mW; NV_PN: 195-2655-000; PATH: I408; PHYS_PAGE: 15; ROT: 0; SEC: 1; SIGNAL_MODEL: nv_res; SKU: NO STUFF; TOL: 0.05 ohm; VER: 1; XY: (-3050,4700)
R188 = R: ASSEMBLY: DEBUG; CDS_LIB: discrete; CDS_PART_NAME: R_0402-100K,1 %,62.5MW,195-0005-000; CDS_PHYS_PART_NAME: R_0402-100K,1 %,62.5MW,195-0005-000-100K,195-0005-000; CDS_SEC: 1; DEVICE_TYPENAME: R_0402-100K1625MW195-0005-000-100K195-0005-000; DRAWING: @P2597_C02_LIB.P2597_C02(SCH_1):PAGE15; MAX_WATTAGE: 62.5mW; NV_PN: 195-0005-000; PATH: I405; PHYS_PAGE: 15; ROT: 0; SEC: 1; SIGNAL_MODEL: nv_res; TOL: 1%; VER: 1; XY: (-3050,4850)
R190 = R: ASSEMBLY: DEBUG; CDS_LIB: discrete; CDS_PART_NAME: R_0402-100K,1 %,62.5MW,195-0005-000; CDS_PHYS_PART_NAME: R_0402-100K,1 %,62.5MW,195-0005-000-100K,195-0005-000; CDS_SEC: 1; DEVICE_TYPENAME: R_0402-100K1625MW195-0005-000-100K195-0005-000; DRAWING: @P2597_C02_LIB.P2597_C02(SCH_1):PAGE15; MAX_WATTAGE: 62.5mW; NV_PN: 195-0005-000; PATH: I414; PHYS_PAGE: 15; ROT: 0; SEC: 1; SIGNAL_MODEL: nv_res; TOL: 1%; VER: 1; XY: (-3950,4600)
R252 = R#1: ASSEMBLY: DEBUG; CDS_LIB: discrete; CDS_PART_NAME: R_0402-1M,5 %,62.5MW,195-0488-000; CDS_PHYS_PART_NAME: R_0402-1M,5 %,62.5MW,195-0488-000-195-0488-000,1M; CDS_SEC: 1; CHIPS_PART_NAME: R; DEVICE_TYPENAME: R_0402-1M5625MW195-0488-000-195-0488-0001M; DRAWING: @P2597_C02_LIB.P2597_C02(SCH_1):PAGE15; MAX_WATTAGE: 62.5mW; NV_PN: 195-0488-000; PATH: I438; PHYS_PAGE: 15; ROT: 0; SEC: 1; SIGNAL_MODEL: nv_res; TOL: 5%; VER: 2; XY: (-600,1600)
R254 = R#1: ASSEMBLY: DEBUG; CDS_LIB: discrete; CDS_PART_NAME: R_0402-10K,5 %,62.5MW,195-0486-000; CDS_PHYS_PART_NAME: R_0402-10K,5 %,62.5MW,195-0486-000-10K,195-0486-000; CDS_SEC: 1; CHIPS_PART_NAME: R; DEVICE_TYPENAME: R_0402-10K5625MW195-0486-000-10K195-0486-000; DRAWING: @P2597_C02_LIB.P2597_C02(SCH_1):PAGE15; MAX_WATTAGE: 62.5mW; NV_PN: 195-0486-000; PATH: I443; PHYS_PAGE: 15; ROT: 0; SEC: 1; SIGNAL_MODEL: nv_res; TOL: 5%; VER: 2; XY: (-600,1900)
R255 = R#1: ASSEMBLY: DEBUG; CDS_LIB: discrete; CDS_PART_NAME: R_0402-10K,5 %,62.5MW,195-0486-000; CDS_PHYS_PART_NAME: R_0402-10K,5 %,62.5MW,195-0486-000-10K,195-0486-000; CDS_SEC: 1; CHIPS_PART_NAME: R; DEVICE_TYPENAME: R_0402-10K5625MW195-0486-000-10K195-0486-000; DRAWING: @P2597_C02_LIB.P2597_C02(SCH_1):PAGE15; MAX_WATTAGE: 62.5mW; NV_PN: 195-0486-000; PATH: I437; PHYS_PAGE: 15; ROT: 0; SEC: 1; SIGNAL_MODEL: nv_res; TOL: 5%; VER: 2; XY: (-1750,2100)
R310 = R: ASSEMBLY: DEBUG; CDS_LIB: discrete; CDS_PART_NAME: R_0402-0OHM,0.05 OHM,62.5MW,195-2655-000; CDS_PHYS_PART_NAME: R_0402-0OHM,0.05 OHM,62.5MW,195-2655-000-0OHM,195-2655-000; CDS_SEC: 1; DEVICE_TYPENAME: R_0402-0OHM005OHM625MW195-2655-000-0OHM195-2655-000; DRAWING: @P2597_C02_LIB.P2597_C02(SCH_1):PAGE15; MAX_WATTAGE: 62.5mW; NV_PN: 195-2655-000; PATH: I475; PHYS_PAGE: 15; ROT: 0; SEC: 1; SIGNAL_MODEL: nv_res; TOL: 0.05 ohm; VER: 1; XY: (-3750,2600)
R311 = R: ASSEMBLY: DEBUG; CDS_LIB: discrete; CDS_PART_NAME: R_0402-0OHM,0.05 OHM,62.5MW,195-2655-000; CDS_PHYS_PART_NAME: R_0402-0OHM,0.05 OHM,62.5MW,195-2655-000-0OHM,195-2655-000; CDS_SEC: 1; DEVICE_TYPENAME: R_0402-0OHM005OHM625MW195-2655-000-0OHM195-2655-000; DRAWING: @P2597_C02_LIB.P2597_C02(SCH_1):PAGE15; MAX_WATTAGE: 62.5mW; NV_PN: 195-2655-000; PATH: I476; PHYS_PAGE: 15; ROT: 0; SEC: 1; SIGNAL_MODEL: nv_res; TOL: 0.05 ohm; VER: 1; XY: (-3800,1950)
R312 = R#1: ASSEMBLY: DEBUG; CDS_LIB: discrete; CDS_PART_NAME: R_0402-0OHM,0.05 OHM,62.5MW,195-2655-000; CDS_PHYS_PART_NAME: R_0402-0OHM,0.05 OHM,62.5MW,195-2655-000-0OHM,195-2655-000; CDS_SEC: 1; CHIPS_PART_NAME: R; DEVICE_TYPENAME: R_0402-0OHM005OHM625MW195-2655-000-0OHM195-2655-000; DRAWING: @P2597_C02_LIB.P2597_C02(SCH_1):PAGE15; MAX_WATTAGE: 62.5mW; NV_PN: 195-2655-000; PATH: I477; PHYS_PAGE: 15; ROT: 0; SEC: 1; SIGNAL_MODEL: nv_res; SKU: NO STUFF; TOL: 0.05 ohm; VER: 2; XY: (-150,2650)
R321 = R#1: ASSEMBLY: DEBUG; CDS_LIB: discrete; CDS_PART_NAME: R_0402-1M,5 %,62.5MW,195-0488-000; CDS_PHYS_PART_NAME: R_0402-1M,5 %,62.5MW,195-0488-000-195-0488-000,1M; CDS_SEC: 1; CHIPS_PART_NAME: R; DEVICE_TYPENAME: R_0402-1M5625MW195-0488-000-195-0488-0001M; DRAWING: @P2597_C02_LIB.P2597_C02(SCH_1):PAGE15; MAX_WATTAGE: 62.5mW; NV_PN: 195-0488-000; PATH: I484; PHYS_PAGE: 15; ROT: 0; SEC: 1; SIGNAL_MODEL: nv_res; TOL: 5%; VER: 2; XY: (-3500,1700)
R324 = R#1: ASSEMBLY: DEBUG; CDS_LIB: discrete; CDS_PART_NAME: R_0402-100K,1 %,62.5MW,195-0005-000; CDS_PHYS_PART_NAME: R_0402-100K,1 %,62.5MW,195-0005-000-100K,195-0005-000; CDS_SEC: 1; CHIPS_PART_NAME: R; DEVICE_TYPENAME: R_0402-100K1625MW195-0005-000-100K195-0005-000; DRAWING: @P2597_C02_LIB.P2597_C02(SCH_1):PAGE15; MAX_WATTAGE: 62.5mW; NV_PN: 195-0005-000; PATH: I487; PHYS_PAGE: 15; ROT: 0; SEC: 1; SIGNAL_MODEL: nv_res; TOL: 1%; VER: 2; XY: (-7450,5600)
R325 = R#1: ASSEMBLY: DEBUG; CDS_LIB: discrete; CDS_PART_NAME: R_0402-100K,1 %,62.5MW,195-0005-000; CDS_PHYS_PART_NAME: R_0402-100K,1 %,62.5MW,195-0005-000-100K,195-0005-000; CDS_SEC: 1; CHIPS_PART_NAME: R; DEVICE_TYPENAME: R_0402-100K1625MW195-0005-000-100K195-0005-000; DRAWING: @P2597_C02_LIB.P2597_C02(SCH_1):PAGE15; MAX_WATTAGE: 62.5mW; NV_PN: 195-0005-000; PATH: I486; PHYS_PAGE: 15; ROT: 0; SEC: 1; SIGNAL_MODEL: nv_res; TOL: 1%; VER: 2; XY: (-7200,5600)
U5 = U_LEVSHFT_3STATE: ASSEMBLY: DEBUG; CDS_LIB: logic; CDS_PART_NAME: U_LEVSHFT_3STATE_SSOP8-SN74LVC2T45,LEVEL SHIFTER,115-0340-000; CDS_PHYS_PART_NAME: U_LEVSHFT_3STATE_SSOP8-SN74LVC2T45,LEVEL SHIFTER,115-0340-000-115-0340-000; CDS_SEC: 1; DEVICE_TYPENAME: U_LEVSHFT_3STATE_SSOP8-SN74LVC2T45LEVELSHIFTER115-0340-000-115-0340-000; DRAWING: @P2597_C02_LIB.P2597_C02(SCH_1):PAGE15; FUNCTION: Level Shifter; NV_NAME: SN74LVC2T45; NV_PN: 115-0340-000; PACK_TYPE: SSOP8; PATH: I416; PHYS_PAGE: 15; ROT: 2; SEC: 1; VER: 4; XY: (-7900,7000)
U6 = U_LEVSHFT_3STATE: ASSEMBLY: DEBUG; CDS_LIB: logic; CDS_PART_NAME: U_LEVSHFT_3STATE_SSOP8-SN74LVC2T45,LEVEL SHIFTER,115-0340-000; CDS_PHYS_PART_NAME: U_LEVSHFT_3STATE_SSOP8-SN74LVC2T45,LEVEL SHIFTER,115-0340-000-115-0340-000; CDS_SEC: 1; DEVICE_TYPENAME: U_LEVSHFT_3STATE_SSOP8-SN74LVC2T45LEVELSHIFTER115-0340-000-115-0340-000; DRAWING: @P2597_C02_LIB.P2597_C02(SCH_1):PAGE15; FUNCTION: Level Shifter; NV_NAME: SN74LVC2T45; NV_PN: 115-0340-000; PACK_TYPE: SSOP8; PATH: I417; PHYS_PAGE: 15; ROT: 2; SEC: 1; VER: 4; XY: (-7900,5250)
U8 = U_SW_ANA_SPDT: ASSEMBLY: DEBUG; CDS_LIB: analog; CDS_PART_NAME: U_SW_ANA_SPDT_BGA10-TS5A22362YZPR,SWITCH - ANALOG,115-1461-000; CDS_PHYS_PART_NAME: U_SW_ANA_SPDT_BGA10-TS5A22362YZPR,SWITCH - ANALOG,115-1461-000-115-1461-000; CDS_SEC: 1; DEVICE_TYPENAME: U_SW_ANA_SPDT_BGA10-TS5A22362YZPRSWITCH-ANALOG115-1461-000-115-1461-000; DRAWING: @P2597_C02_LIB.P2597_C02(SCH_1):PAGE15; FUNCTION: Switch - Analog; NV_NAME: TS5A22362YZPR; NV_PN: 115-1461-000; PACK_TYPE: BGA10; PATH: I369; PHYS_PAGE: 15; ROT: 0; SEC: 1; SEC_TYPE: BGA10; VER: 3; XY: (-8050,2450)
U12 = U_LEVSHFT_3STATE: ASSEMBLY: DEBUG; CDS_LIB: logic; CDS_PART_NAME: U_LEVSHFT_3STATE_SSOP8-SN74LVC2T45,LEVEL SHIFTER,115-0340-000; CDS_PHYS_PART_NAME: U_LEVSHFT_3STATE_SSOP8-SN74LVC2T45,LEVEL SHIFTER,115-0340-000-115-0340-000; CDS_SEC: 1; DEVICE_TYPENAME: U_LEVSHFT_3STATE_SSOP8-SN74LVC2T45LEVELSHIFTER115-0340-000-115-0340-000; DRAWING: @P2597_C02_LIB.P2597_C02(SCH_1):PAGE15; FUNCTION: Level Shifter; NV_NAME: SN74LVC2T45; NV_PN: 115-0340-000; PACK_TYPE: SSOP8; PATH: I174; PHYS_PAGE: 15; ROT: 2; SEC: 1; VER: 4; XY: (-2950,6150)
U14 = U_LEVSHFT_3STATE: ASSEMBLY: DEBUG; CDS_LIB: logic; CDS_PART_NAME: U_LEVSHFT_3STATE_SSOP8-SN74LVC2T45,LEVEL SHIFTER,115-0340-000; CDS_PHYS_PART_NAME: U_LEVSHFT_3STATE_SSOP8-SN74LVC2T45,LEVEL SHIFTER,115-0340-000-115-0340-000; CDS_SEC: 1; DEVICE_TYPENAME: U_LEVSHFT_3STATE_SSOP8-SN74LVC2T45LEVELSHIFTER115-0340-000-115-0340-000; DRAWING: @P2597_C02_LIB.P2597_C02(SCH_1):PAGE15; FUNCTION: Level Shifter; NV_NAME: SN74LVC2T45; NV_PN: 115-0340-000; PACK_TYPE: SSOP8; PATH: I104; PHYS_PAGE: 15; ROT: 0; SEC: 1; VER: 4; XY: (-2950,5400)
U30 = U_I2C_PCA9515A: ASSEMBLY: DEBUG; CDS_LIB: digital; CDS_PART_NAME: U_I2C_PCA9515A_MSOP8-PCA9515ADP,LEVEL SHIFTER,115-0401-000; CDS_PHYS_PART_NAME: U_I2C_PCA9515A_MSOP8-PCA9515ADP,LEVEL SHIFTER,115-0401-000-115-0401-000; CDS_SEC: 1; DEVICE_TYPENAME: U_I2C_PCA9515A_MSOP8-PCA9515ADPLEVELSHIFTER115-0401-000-115-0401-000; DRAWING: @P2597_C02_LIB.P2597_C02(SCH_1):PAGE15; FUNCTION: Level Shifter; NV_NAME: PCA9515ADP; NV_PN: 115-0401-000; PACK_TYPE: MSOP8; PATH: I465; PHYS_PAGE: 15; ROT: 0; SEC: 1; SEC_TYPE: MSOP8; VER: 1; XY: (-2200,3200)

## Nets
GND: C48.2 C51.2 C54.2 C96.1 C98.2 C103.2 C104.1 C160.2 J17.1 Q10.2(S) Q24.2(S) Q38.2(S) Q38.5(S) Q40.2(S) R84.2 R99.2 R174.2 R177.2 R187.2 R252.2 R312.2 R321.2 U5.4(GND) U5.5(DIR) U6.4(GND) U8.D2(GND) U12.4(GND) U12.5(DIR) U14.4(GND) U30.4(GND) ; also on sheet 1 2 3 4 5 6 7 9 10 11 12 13 14 15 16 17 18 20 21 22 23 24 25 26 30
VDD_1V8: C51.1 C96.2 C104.2 R74.2 R188.2 R190.1 U5.8(VCCB) U6.8(VCCB) U12.8(VCCB) U14.1(VCCA) ; also on sheet 4 5 9 10 12 13 16 17 18 20 22 24 30
VDD_3V3_SYS: C48.1 C54.1 C98.1 C103.1 C160.1 R83.2 R96.1 R255.1 R324.1 R325.1 U5.1(VCCA) U6.1(VCCA) U8.A2(VCC) U12.1(VCCA) U14.8(VCCB) U30.8(VCC) ; also on sheet 1 2 3 4 5 6 12 13 17 18 23 24 25
CAM_UART1_CTS: R175.1 ; also on sheet 16
CAM_UART1_PSNT_L: Q24.1(G) R190.2 ; also on sheet 16
CAM_UART1_RTS: R165.1 ; also on sheet 16
CAM_UART1_RXD: R178.1 ; also on sheet 16
CAM_UART1_TXD: R168.1 ; also on sheet 16
CAM_UART_DIR: Q24.3(D) R187.1 R188.1 U14.5(DIR)
DBG_I2C_EN: Q36.3(D) Q37.3(D) Q38.6(D) R312.1 U30.5(EN)
DBG_I2C_EN_L: Q38.1(G) Q38.4(D) R255.2
DBG_PM342_I2C_SCL_3V3: U30.7(SCL1) ; also on sheet 12
DBG_PM342_I2C_SDA_3V3: U30.6(SDA1) ; also on sheet 12
DBG_UART_SEL: R92.2 R96.2 R99.1 U8.D1(IN2) U8.D3(IN1)
FLASH_STROBE: R311.1 ; also on sheet 16 29
FLASH_STROBE_G: Q37.1(G) R311.2 R321.1
I2C_GP1_CLK_3V3: U30.2(SCL0) ; also on sheet 2 3 12 13 17 18 30
I2C_GP1_DAT_3V3: U30.3(SDA0) ; also on sheet 2 3 12 13 17 18 30
PM_BUS_SEL: R310.1 ; also on sheet 12
PM_BUS_SEL_G: Q36.1(G) R310.2
RXD_HDR_1V8: R81.1 R82.1 U6.6(B2)
SNN_UART_HDR_P3: J17.3
TXD_HDR_1V8: R79.2 R80.2 U5.6(B2)
UART0_CTS: U6.7(B1) ; also on sheet 12 28
UART0_RTS: U5.7(B1) ; also on sheet 12 28
UART0_RXD: R102.1 U8.B1(COM2) ; also on sheet 28
UART0_RXD_DBG_1V8: U8.A1(NO2) ; also on sheet 12
UART0_RXD_HDR_1V8: R81.2 R102.2 U8.C1(NC2)
UART0_TXD: R89.1 U8.B3(COM1) ; also on sheet 28
UART0_TXD_DBG_1V8: U8.A3(NO1) ; also on sheet 12
UART0_TXD_HDR_1V8: R80.1 R89.2 U8.C3(NC1)
UART1_CTS: R175.2 U14.2(A1) ; also on sheet 30
UART1_CTS_3V3_L: J17.6 R174.1 U14.7(B1)
UART1_CTS_HDR_3V3: R325.2 U6.2(A1) ; also on sheet 18
UART1_DIR: Q10.3(D) R83.1 R84.1 U6.5(DIR)
UART1_DIR_G: Q10.1(G) R62.2
UART1_RTS: R165.2 U12.7(B1) ; also on sheet 30
UART1_RTS_3V3_L: J17.2 U12.2(A1)
UART1_RTS_HDR_3V3: U5.2(A1) ; also on sheet 18
UART1_RXD: R178.2 U14.3(A2) ; also on sheet 30
UART1_RXD_3V3: J17.4 R177.1 U14.6(B2)
UART1_RXD_HDR_3V3: R324.2 U6.3(A2) ; also on sheet 18
UART1_TXD: R168.2 U12.6(B2) ; also on sheet 30
UART1_TXD_3V3: J17.5 U12.3(A2)
UART1_TXD_HDR_3V3: U5.3(A2) ; also on sheet 18
UART3_RXD: R82.2 ; also on sheet 30
UART3_TXD: R74.1 R79.1 ; also on sheet 30
VAUX_5V: R62.1 R92.1 R254.1 ; also on sheet 12
VAUX_5V_G: Q38.3(G) Q40.1(G) R252.1 R254.2
VAUX_5V_L: Q36.2(S) Q37.2(S) Q40.3(D)

Not connected (* = marked no-connect by the designer): U30 1(NC)

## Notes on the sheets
sheet 19
- A
- B
- C
- D
- E
- F
- G
- H
- 1
- 1
- SERIAL PORT
- ref:  http://www.adafruit.com/datasheets/FT232_Model.pdf
- ref:  http://www.adafruit.com/products/284
- NS
- Device side
- CTS
- USB +5v
- TXD
- RXD
- RTS
- 2
- 2
- DIR
- Vih = 0.7*VCCA
- = 1.26v
- DIR
- Vil = 0.3*VCCA
- 0 | B -> A
- DIR
- = 0.54v
- 1 | A -> B
- 0 | B -> A
- DIR
- 1 | A -> B
- Vih = 0.7*VCCA
- = 1.26v
- Vil = 0.3*VCCA
- = 0.54v
- NS
- 3
- NS
- 3
- DBG I2C GATE
- UART MUX
- When the 60-pin debug connector is being used
- UART is routed to the 60-pin debug connector
- When the 60-pin debug connector is NOT being used
- 4
- 4
- UART is routed to the 40pin stake pin header
- NS
- Debug bus only enabled if:
- PM342 pluged in and powered AND
- PM_BUS_SEL=0  AND
- FLASH_STROBE=0
- 5
- 5
- NVIDIA CORPORATION
- 2701 SAN TOMAS EXPRESSWAY
- ASSEMBLY
- <ASSEMBLY_DESCRIPTION>
- SANTA CLARA, CA 95050, USA
- PAGE DETAIL
- Serial port and JTAG
- NV_PN
- 600-82597-BASE-900
- ALL NVIDIA DESIGN SPECIFICATIONS, REFERENCE SPECIFICATIONS, REFERENCE BOARDS, FILES, DRAWINGS, DIAGNOSTICS, LISTS AND OTHER DOCUMENTS OR INFORMATION (TOGETHER AND SEPARATELY, 'MATERIALS') ARE BEING PROVIDED 'AS IS'. THE MATERIALS MAY
- CONTAIN KNOWN AND UNKNOWN VIOLATIONS OR DEVIATIONS OF INDUSTRY STANDARDS AND SPECIFICATIONS. NVIDIA MAKES NO WARRANTIES, EXPRESSED, IMPLIED, STATUTORY OR OTHERWISE WITH RESPECT TO THE MATERIALS OR OTHERWISE, AND EXPRESSLY DISCLAIMS ALL
- PCB REV
- P2597-C02
- PAGE
- 15 OF 34
- IMPLIED WARRANTIES INCLUDING, WITHOUT LIMITATION, THE WARRANTIES OF DESIGN, OF NONINFRINGEMENT, MERCHANTABILITY OR FITNESS FOR A PARTICULAR PURPOSE, OR ARISING FROM A COURSE OF DEALING, TRADE USAGE, TRADE PRACTICE, OR INDUSTRY STANDARDS.
- BOM REV
- A
- DATE
- 23-OCT-2017
- A
- B
- C
- D
- E
- F
- G
- H
